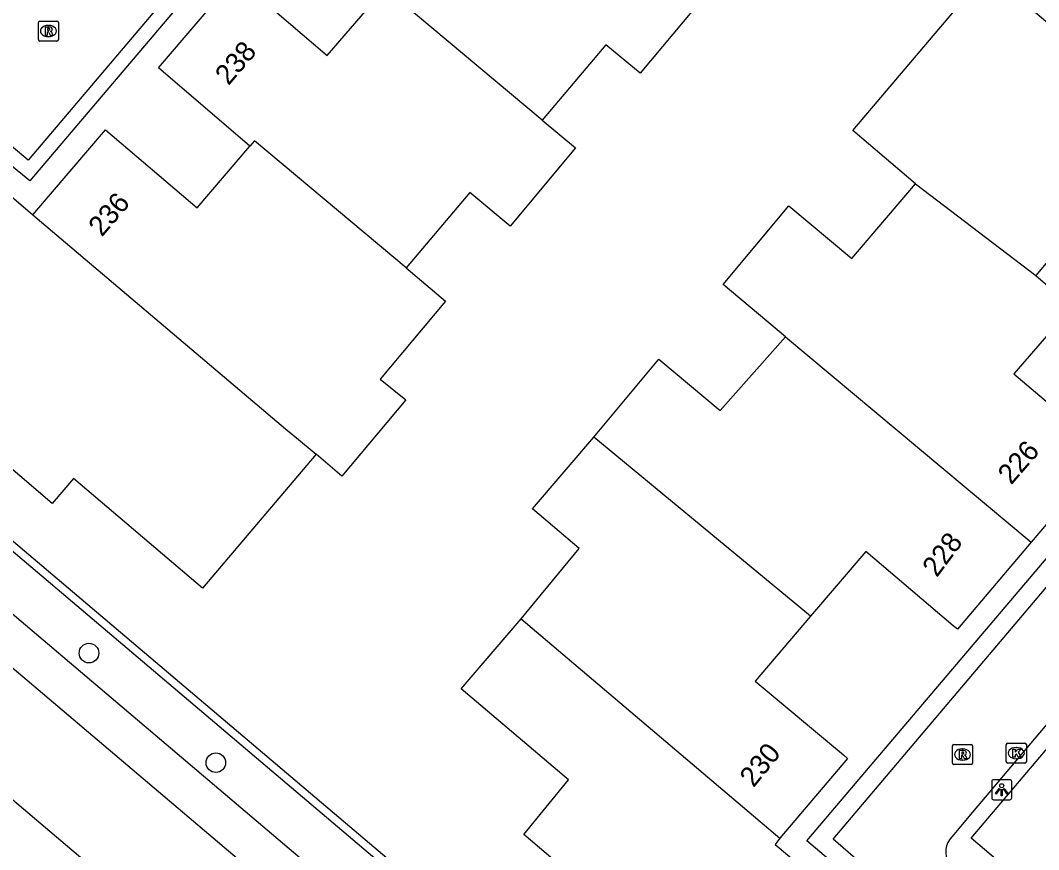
# Model space of a CAD drawing. Extents: x 156414 to 157775, y 382335 to 383765.
# Drawn here: x 157040.3 to 157091, y 382653.8 to 382695.1 of the extents above; entities that cross this region are included whole.
import ezdxf

# ---------------------------------------------------------------- set-up
doc = ezdxf.new("R2010")
doc.units = 0
for name, color, linetype in [('IMGEO_Boom', 7, 'Continuous'), ('IMGEO_Haag', 7, 'Continuous'), ('IMGEO_Kolk', 7, 'Continuous'), ('IMGEO_Lichtpunt', 7, 'Continuous'), ('IMGEO_Pand', 7, 'Continuous'), ('IMGEO_Pand_nummerreeks', 7, 'Continuous'), ('IMGEO_Parkeervlak_open', 7, 'Continuous'), ('IMGEO_Rijbaan_lokaal_open', 7, 'Continuous'), ('IMGEO_Rioolput', 7, 'Continuous'), ('IMGEO_Voetpad_open', 7, 'Continuous')]:
    doc.layers.add(name, color=color, linetype=linetype)

msp = doc.modelspace()

# ---------------------------------------------------------------- linework, layer by layer
at = {"layer": 'IMGEO_Boom'}
for centre in [(157043.693, 382663.586), (157050.015, 382658.127)]:
    msp.add_circle(centre, 0.489, dxfattribs=at)
at = {"layer": 'IMGEO_Haag'}
for points in [[(157032.158, 382675.203), (157069.276, 382643.763)], [(157032.409, 382675.515), (157069.523, 382644.078)]]:
    msp.add_lwpolyline(points, dxfattribs=at)
at = {"layer": 'IMGEO_Kolk'}
for p, q in [((157089.399, 382658.178), (157089.399, 382659.03)), ((157089.474, 382659.104), (157090.326, 382659.104)), ((157089.887, 382658.884), (157089.912, 382658.884)), ((157090.4, 382659.03), (157090.4, 382658.178)), ((157089.91, 382658.324), (157089.885, 382658.324)), ((157090.326, 382658.104), (157089.474, 382658.104))]:
    msp.add_line(p, q, dxfattribs=at)
for points in [[(157089.399, 382658.178), (157089.399, 382659.03)], [(157089.474, 382659.104), (157090.326, 382659.104)], [(157090.4, 382659.03), (157090.4, 382658.178)], [(157089.72, 382658.804), (157089.843, 382658.804), (157089.843, 382658.653), (157089.973, 382658.804), (157090.137, 382658.804), (157089.991, 382658.653), (157090.144, 382658.404), (157089.992, 382658.404), (157089.907, 382658.568), (157089.843, 382658.501), (157089.843, 382658.404), (157089.72, 382658.404), (157089.72, 382658.804)], [(157090.326, 382658.104), (157089.474, 382658.104)]]:
    msp.add_lwpolyline(points, dxfattribs=at)
for centre, start, end in [((157089.476, 382659.028), 91.552, 178.448), ((157089.476, 382659.028), 91.552, 178.448), ((157090.324, 382659.028), 1.552, 88.448), ((157090.324, 382659.028), 1.552, 88.448), ((157089.476, 382658.18), 181.552, 268.448), ((157089.476, 382658.18), 181.552, 268.448), ((157090.324, 382658.18), 271.552, 358.448), ((157090.324, 382658.18), 271.552, 358.448)]:
    msp.add_arc(centre, 0.0765, start, end, dxfattribs=at)
for centre, major_axis, ratio, start_param, end_param in [((157089.886, 382658.604), (-0.387, 0.002), 0.722429, 4.712389, 7.853982), ((157089.911, 382658.604), (-0.39, 0.002), 0.717154, 1.570796, 4.712389)]:
    msp.add_ellipse(centre, major_axis=major_axis, ratio=ratio, start_param=start_param, end_param=end_param, dxfattribs=at)
at = {"layer": 'IMGEO_Lichtpunt'}
for p, q in [((157088.673, 382657.183), (157088.673, 382656.376)), ((157088.673, 382657.183), (157088.673, 382656.376)), ((157089.575, 382657.278), (157088.767, 382657.278)), ((157089.575, 382657.278), (157088.767, 382657.278)), ((157089.669, 382656.376), (157089.669, 382657.183)), ((157089.669, 382656.376), (157089.669, 382657.183)), ((157088.767, 382656.282), (157089.575, 382656.282)), ((157088.767, 382656.282), (157089.575, 382656.282))]:
    msp.add_line(p, q, dxfattribs=at)
for points in [[(157089.047, 382656.847), (157089.086, 382656.819), (157088.898, 382656.557), (157088.86, 382656.584), (157089.047, 382656.847)], [(157089.149, 382656.799), (157089.196, 382656.799), (157089.196, 382656.477), (157089.149, 382656.477), (157089.149, 382656.799)], [(157089.259, 382656.819), (157089.297, 382656.846), (157089.484, 382656.584), (157089.445, 382656.556), (157089.259, 382656.819)]]:
    msp.add_lwpolyline(points, dxfattribs=at)
msp.add_circle((157089.172, 382656.981), 0.0994, dxfattribs=at)
for centre, start, end in [((157088.767, 382657.183), 90, 180), ((157088.767, 382657.183), 90, 180), ((157089.575, 382657.183), 0, 90), ((157089.575, 382657.183), 0, 90), ((157088.767, 382656.376), 180, 270), ((157088.767, 382656.376), 180, 270), ((157089.575, 382656.376), 270, 0), ((157089.575, 382656.376), 270, 360)]:
    msp.add_arc(centre, 0.0946, start, end, dxfattribs=at)
at = {"layer": 'IMGEO_Pand'}
for points in [[(157072.893, 382697.635), (157074.416, 382696.377), (157071.151, 382692.475), (157069.451, 382693.89), (157066.27, 382690.143)], [(157084.877, 382686.973), (157081.753, 382689.629), (157088.459, 382697.537), (157091.586, 382694.885)], [(157051.716, 382688.85), (157047.155, 382692.749), (157051.009, 382697.256), (157051.145, 382697.14), (157055.569, 382693.358), (157058.201, 382696.436)], [(157066.27, 382690.143), (157058.435, 382696.714), (157058.201, 382696.436)], [(157066.27, 382690.143), (157067.939, 382688.765), (157064.679, 382684.86), (157062.675, 382686.539), (157059.5, 382682.78)], [(157040.892, 382685.421), (157044.517, 382689.663), (157049.078, 382685.764), (157051.716, 382688.85)], [(157059.5, 382682.78), (157051.935, 382689.104), (157051.716, 382688.85)], [(157055.012, 382673.5), (157049.354, 382666.815), (157042.925, 382672.288), (157041.863, 382671.04), (157038.623, 382673.791), (157039.683, 382675.041), (157035.775, 382678.36), (157031.438, 382682.057), (157037.091, 382688.67), (157040.892, 382685.421)], [(157078.403, 382679.344), (157075.29, 382681.947), (157078.557, 382685.87), (157081.708, 382683.246), (157084.877, 382686.973)], [(157084.877, 382686.973), (157090.874, 382682.406)], [(157040.892, 382685.421), (157053.494, 382674.765), (157054.032, 382674.317), (157055.012, 382673.5)], [(157103.749, 382684.575), (157099.899, 382680.038), (157093.454, 382685.474), (157090.874, 382682.406)], [(157059.5, 382682.78), (157061.459, 382681.126), (157058.209, 382677.239), (157059.474, 382676.198), (157056.298, 382672.4), (157055.012, 382673.5)], [(157090.874, 382682.406), (157092.681, 382680.833), (157092.389, 382680.498), (157089.779, 382677.5), (157094.206, 382673.746), (157094.424, 382673.561), (157090.647, 382669.106)], [(157068.85, 382674.35), (157072.092, 382678.238), (157075.141, 382675.666), (157078.403, 382679.344)], [(157078.403, 382679.344), (157090.647, 382669.106)], [(157065.234, 382665.289), (157068.122, 382668.791), (157065.791, 382670.77), (157068.85, 382674.35)], [(157079.646, 382665.434), (157068.85, 382674.35)], [(157090.647, 382669.106), (157086.972, 382664.773), (157086.76, 382664.952), (157082.396, 382668.654), (157079.646, 382665.434)], [(157079.646, 382665.434), (157076.887, 382662.197), (157081.281, 382658.516), (157081.486, 382658.344), (157078.125, 382654.361)], [(157078.125, 382654.361), (157077.888, 382654.049), (157081.687, 382650.856), (157076.065, 382644.201), (157070.314, 382649.055), (157070.928, 382649.821), (157065.364, 382654.546), (157067.587, 382657.281), (157062.243, 382661.812), (157065.234, 382665.289)], [(157065.234, 382665.289), (157078.125, 382654.361)]]:
    msp.add_lwpolyline(points, dxfattribs=at)
at = {"layer": 'IMGEO_Parkeervlak_open'}
msp.add_lwpolyline([(157091.638, 382650.975), (157087.643, 382654.359), (157092.825, 382660.479), (157094.053, 382659.418), (157094.546, 382660.003), (157092.683, 382661.545)], dxfattribs=at)
at = {"layer": 'IMGEO_Rijbaan_lokaal_open'}
for points in [[(157031.358, 382696.042), (157029.108, 382697.955), (157065.152, 382740.481), (157076.663, 382730.587), (157040.671, 382688.15), (157038.422, 382690.03)], [(157082.895, 382652.477), (157080.769, 382654.32), (157116.675, 382696.742), (157128.088, 382687.021), (157092.121, 382644.588), (157089.934, 382646.493)], [(157062.793, 382636.854), (157025.955, 382668.078)], [(157092.683, 382661.545), (157087.537, 382655.446), (157087.049, 382654.862), (157086.604, 382654.331), (157086.482, 382654.155)]]:
    msp.add_lwpolyline(points, dxfattribs=at)
msp.add_arc((157087.387, 382653.713), 1.007, 153.9779, 233.5772, dxfattribs=at)
at = {"layer": 'IMGEO_Rioolput'}
for p, q in [((157041.172, 382694.152), (157041.172, 382695.004)), ((157041.247, 382695.078), (157042.099, 382695.078)), ((157041.66, 382694.858), (157041.685, 382694.858)), ((157042.173, 382695.004), (157042.173, 382694.152)), ((157042.099, 382694.078), (157041.247, 382694.078)), ((157041.683, 382694.298), (157041.658, 382694.298)), ((157086.716, 382658.108), (157086.716, 382658.96)), ((157086.791, 382659.034), (157087.643, 382659.034)), ((157087.717, 382658.96), (157087.717, 382658.108)), ((157087.204, 382658.814), (157087.229, 382658.814)), ((157087.643, 382658.034), (157086.791, 382658.034)), ((157087.227, 382658.254), (157087.202, 382658.254))]:
    msp.add_line(p, q, dxfattribs=at)
for points in [[(157041.172, 382694.152), (157041.172, 382695.004)], [(157041.247, 382695.078), (157042.099, 382695.078)], [(157042.173, 382695.004), (157042.173, 382694.152)], [(157041.761, 382694.776), (157041.509, 382694.778), (157041.509, 382694.378)], [(157041.509, 382694.378), (157041.633, 382694.378), (157041.633, 382694.54), (157041.644, 382694.54)], [(157041.687, 382694.697), (157041.633, 382694.697), (157041.633, 382694.616)], [(157041.633, 382694.616), (157041.685, 382694.616)], [(157041.691, 382694.511), (157041.762, 382694.378), (157041.902, 382694.378), (157041.837, 382694.504)], [(157042.099, 382694.078), (157041.247, 382694.078)], [(157086.716, 382658.108), (157086.716, 382658.96)], [(157086.791, 382659.034), (157087.643, 382659.034)], [(157087.717, 382658.96), (157087.717, 382658.108)], [(157087.305, 382658.732), (157087.053, 382658.734), (157087.053, 382658.334)], [(157087.053, 382658.334), (157087.177, 382658.334), (157087.177, 382658.496), (157087.188, 382658.496)], [(157087.231, 382658.653), (157087.177, 382658.653), (157087.177, 382658.572)], [(157087.177, 382658.572), (157087.229, 382658.572)], [(157087.235, 382658.467), (157087.306, 382658.334), (157087.446, 382658.334), (157087.381, 382658.46)], [(157087.643, 382658.034), (157086.791, 382658.034)]]:
    msp.add_lwpolyline(points, dxfattribs=at)
for centre, radius, start, end in [((157041.249, 382695.002), 0.0765, 91.552, 178.448), ((157041.249, 382695.002), 0.0765, 91.552, 178.448), ((157042.097, 382695.002), 0.0765, 1.552, 88.448), ((157042.097, 382695.002), 0.0765, 1.552, 88.448), ((157041.643, 382694.487), 0.0533, 26.0293, 88.6989), ((157041.669, 382694.805), 0.19, 274.7715, 282.9687), ((157041.693, 382694.601), 0.0964, 77.0061, 93.1865), ((157041.707, 382694.658), 0.0378, 276.6634, 79.6772), ((157041.76, 382694.666), 0.109, 350.3612, 89.416), ((157041.758, 382694.666), 0.112, 277.5842, 350.9817), ((157041.742, 382694.451), 0.108, 29.5134, 73.7905), ((157041.249, 382694.154), 0.0765, 181.552, 268.448), ((157041.249, 382694.154), 0.0765, 181.552, 268.448), ((157042.097, 382694.154), 0.0765, 271.552, 358.448), ((157042.097, 382694.154), 0.0765, 271.552, 358.448), ((157086.793, 382658.958), 0.0765, 91.552, 178.448), ((157086.793, 382658.958), 0.0765, 91.552, 178.448), ((157087.641, 382658.958), 0.0765, 1.552, 88.448), ((157087.641, 382658.958), 0.0765, 1.552, 88.448), ((157087.187, 382658.443), 0.0533, 26.0293, 88.6989), ((157087.213, 382658.761), 0.19, 274.7715, 282.9687), ((157087.237, 382658.557), 0.0964, 77.0061, 93.1865), ((157087.251, 382658.614), 0.0378, 276.6634, 79.6772), ((157087.304, 382658.622), 0.109, 350.3612, 89.416), ((157087.302, 382658.622), 0.112, 277.5842, 350.9817), ((157087.286, 382658.407), 0.108, 29.5134, 73.7905), ((157086.793, 382658.11), 0.0765, 181.552, 268.448), ((157086.793, 382658.11), 0.0765, 181.552, 268.448), ((157087.641, 382658.11), 0.0765, 271.552, 358.448), ((157087.641, 382658.11), 0.0765, 271.552, 358.448)]:
    msp.add_arc(centre, radius, start, end, dxfattribs=at)
for centre, major_axis, ratio, start_param, end_param in [((157041.659, 382694.578), (-0.387, 0.002), 0.722429, 4.712389, 7.853982), ((157041.684, 382694.578), (-0.39, 0.002), 0.717154, 1.570796, 4.712389), ((157087.203, 382658.534), (-0.387, 0.002), 0.722429, 4.712389, 7.853982), ((157087.228, 382658.534), (-0.39, 0.002), 0.717154, 1.570796, 4.712389)]:
    msp.add_ellipse(centre, major_axis=major_axis, ratio=ratio, start_param=start_param, end_param=end_param, dxfattribs=at)
at = {"layer": 'IMGEO_Voetpad_open'}
for points in [[(157030.846, 382695.439), (157028.026, 382697.895), (157065.098, 382741.643), (157077.821, 382730.77), (157040.747, 382687.119), (157037.92, 382689.412)], [(157082.363, 382651.78), (157079.465, 382654.239), (157116.559, 382697.961), (157129.305, 382687.146), (157092.239, 382643.346), (157089.335, 382645.82)], [(157067.778, 382641.856), (157030.662, 382673.34)], [(157029.146, 382671.937), (157066.118, 382640.609)]]:
    msp.add_lwpolyline(points, dxfattribs=at)

# ---------------------------------------------------------------- texts
at = {"layer": 'IMGEO_Pand_nummerreeks'}
for s, rotation, p in [('238', 49.4077, (157050.646, 382691.832)), ('236', 49.5207, (157044.338, 382684.287)), ('226', 49.0373, (157089.644, 382671.933)), ('228', 53.3746, (157085.94, 382667.321)), ('230', 50.9463, (157076.807, 382656.851))]:
    msp.add_text(s, height=1, rotation=rotation, dxfattribs=at).set_placement(p)

doc.saveas('drawing.dxf')
